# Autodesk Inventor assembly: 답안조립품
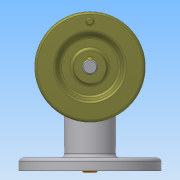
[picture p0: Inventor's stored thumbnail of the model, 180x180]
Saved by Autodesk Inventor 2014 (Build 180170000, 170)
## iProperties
Created: 2018-11
Part Number: 답안조립품
Document SubType Name: Assembly
Designer: 703
Author: 703
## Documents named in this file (18)
- C:\Users\user\Desktop\381107V1012\답안조립품.iam
- C:\Users\user\Desktop\381107V1012\V-벨트풀리.ipt
- C:\Users\user\Desktop\381107V1012\가변스프링.ipt
- C:\Users\user\Desktop\381107V1012\개스킷.ipt
- C:\Users\user\Desktop\381107V1012\뒤커버.ipt
- C:\Users\user\Desktop\381107V1012\멈춤나사 M3x8.ipt
- C:\Users\user\Desktop\381107V1012\베어링 6201.ipt
- C:\Users\user\Desktop\381107V1012\베어링 6202.ipt
- C:\Users\user\Desktop\381107V1012\본체.ipt
- C:\Users\user\Desktop\381107V1012\본체커버.ipt
- C:\Users\user\Desktop\381107V1012\볼트 M3x0.5x8.ipt
- C:\Users\user\Desktop\381107V1012\슬라이드.ipt
- C:\Users\user\Desktop\381107V1012\앞커버.ipt
- C:\Users\user\Desktop\381107V1012\오일 실 12 22 7.ipt
- 오일 실 12 22 7.ipt
- C:\Users\user\Desktop\381107V1012\키 4x4x18.ipt
- 키 4x4x18.ipt
- C:\Users\user\Desktop\381107V1012\편심축.ipt
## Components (4 placed, 3 different names)
1. V-벨트풀리:1 — 플러쉬:1
2. 가변스프링:1
3. 개스킷:1
4. 개스킷:2
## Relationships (1: Flush 1)
- 플러쉬:1 [Flush]: V-벨트풀리:1
